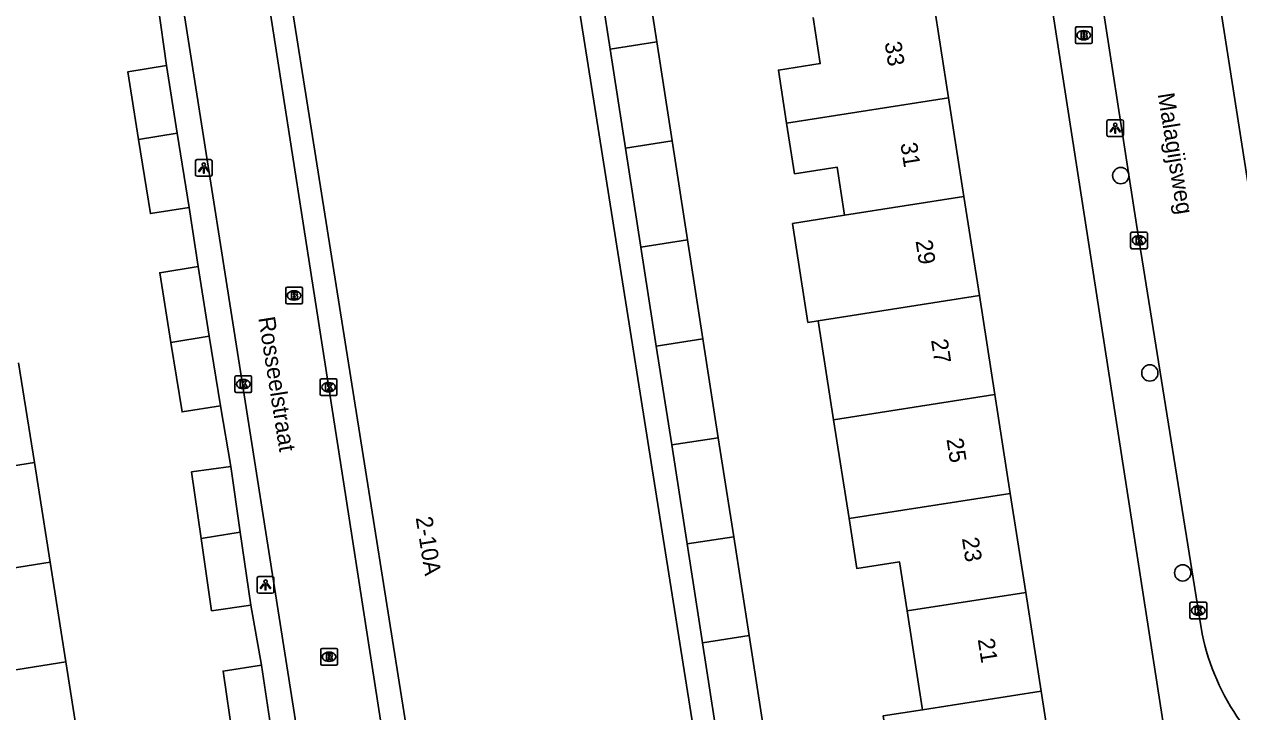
# Model space of a CAD drawing. Extents: x 160077 to 160945, y 386481 to 387498.
# Drawn here: x 160547.5 to 160620.3, y 387375.4 to 387416.6 of the extents above; entities that cross this region are included whole.
import ezdxf

# ---------------------------------------------------------------- set-up
doc = ezdxf.new("R2010")
doc.units = 0
for name, color, linetype in [('IMGEO_Boom', 7, 'Continuous'), ('IMGEO_Brandkraan', 7, 'Continuous'), ('IMGEO_Kolk', 7, 'Continuous'), ('IMGEO_Lichtpunt', 7, 'Continuous'), ('IMGEO_Openbare_ruimte_label', 7, 'Continuous'), ('IMGEO_Pand', 7, 'Continuous'), ('IMGEO_Pand_nummerreeks', 7, 'Continuous'), ('IMGEO_Rijbaan_lokaal_open', 7, 'Continuous'), ('IMGEO_Rioolput', 7, 'Continuous'), ('IMGEO_Voetpad_open', 7, 'Continuous')]:
    doc.layers.add(name, color=color, linetype=linetype)

msp = doc.modelspace()

# ---------------------------------------------------------------- linework, layer by layer
at = {"layer": 'IMGEO_Boom'}
for centre in [(160613.231, 387407.572), (160614.973, 387395.746), (160616.944, 387383.768)]:
    msp.add_circle(centre, 0.489, dxfattribs=at)
at = {"layer": 'IMGEO_Brandkraan'}
for p, q in [((160610.507, 387415.558), (160610.507, 387416.41)), ((160610.582, 387416.484), (160611.434, 387416.484)), ((160610.995, 387416.264), (160611.02, 387416.264)), ((160611.508, 387416.41), (160611.508, 387415.558)), ((160611.434, 387415.484), (160610.582, 387415.484)), ((160611.018, 387415.704), (160610.993, 387415.704)), ((160563.241, 387400.891), (160564.093, 387400.891)), ((160563.166, 387399.965), (160563.166, 387400.817)), ((160563.677, 387400.111), (160563.652, 387400.111)), ((160563.654, 387400.671), (160563.679, 387400.671)), ((160564.167, 387400.817), (160564.167, 387399.965)), ((160564.093, 387399.891), (160563.241, 387399.891))]:
    msp.add_line(p, q, dxfattribs=at)
for points in [[(160610.507, 387415.558), (160610.507, 387416.41)], [(160610.582, 387416.484), (160611.434, 387416.484)], [(160610.855, 387416.184), (160610.855, 387415.784), (160611.068, 387415.784)], [(160611.086, 387416.184), (160610.855, 387416.184)], [(160611.508, 387416.41), (160611.508, 387415.558)], [(160611.434, 387415.484), (160610.582, 387415.484)], [(160611.034, 387416.103), (160610.98, 387416.103), (160610.98, 387416.027)], [(160610.98, 387416.027), (160611.033, 387416.027)], [(160611.042, 387415.951), (160610.98, 387415.951), (160610.98, 387415.87)], [(160610.98, 387415.87), (160611.042, 387415.87)], [(160563.241, 387400.891), (160564.093, 387400.891)], [(160563.166, 387399.965), (160563.166, 387400.817)], [(160563.514, 387400.591), (160563.514, 387400.191), (160563.727, 387400.191)], [(160563.745, 387400.591), (160563.514, 387400.591)], [(160563.693, 387400.51), (160563.639, 387400.51), (160563.639, 387400.434)], [(160563.639, 387400.434), (160563.692, 387400.434)], [(160563.701, 387400.358), (160563.639, 387400.358), (160563.639, 387400.277)], [(160563.639, 387400.277), (160563.701, 387400.277)], [(160564.167, 387400.817), (160564.167, 387399.965)], [(160564.093, 387399.891), (160563.241, 387399.891)]]:
    msp.add_lwpolyline(points, dxfattribs=at)
for centre, radius, start, end in [((160610.584, 387416.408), 0.0765, 91.55205, 178.44795), ((160610.584, 387416.408), 0.0765, 91.55205, 178.44795), ((160611.09, 387416.039), 0.145, 59.4692, 91.53667), ((160611.115, 387416.086), 0.0922, 285.51372, 58.15012), ((160611.432, 387416.408), 0.0765, 1.55205, 88.44795), ((160611.432, 387416.408), 0.0765, 1.55205, 88.44795), ((160610.584, 387415.56), 0.0765, 181.55205, 268.44795), ((160610.584, 387415.56), 0.0765, 181.55205, 268.44795), ((160611.035, 387416.065), 0.0379, 267.82845, 90.93552), ((160611.043, 387415.91), 0.0404, 269.87594, 90.50774), ((160611.074, 387416.035), 0.251, 268.66757, 293.53466), ((160611.12, 387415.894), 0.105, 301.31148, 78.98903), ((160611.432, 387415.56), 0.0765, 271.55205, 358.44795), ((160611.432, 387415.56), 0.0765, 271.55205, 358.44795), ((160563.243, 387400.815), 0.0765, 91.55205, 178.44795), ((160563.243, 387400.815), 0.0765, 91.55205, 178.44795), ((160564.091, 387400.815), 0.0765, 1.55205, 88.44795), ((160564.091, 387400.815), 0.0765, 1.55205, 88.44795), ((160563.694, 387400.472), 0.0379, 267.82845, 90.93552), ((160563.702, 387400.317), 0.0404, 269.87594, 90.50774), ((160563.733, 387400.442), 0.251, 268.66757, 293.53466), ((160563.749, 387400.446), 0.145, 59.4692, 91.53667), ((160563.774, 387400.493), 0.0922, 285.51372, 58.15012), ((160563.779, 387400.301), 0.105, 301.31148, 78.98903), ((160563.243, 387399.967), 0.0765, 181.55205, 268.44795), ((160563.243, 387399.967), 0.0765, 181.55205, 268.44795), ((160564.091, 387399.967), 0.0765, 271.55205, 358.44795), ((160564.091, 387399.967), 0.0765, 271.55205, 358.44795)]:
    msp.add_arc(centre, radius, start, end, dxfattribs=at)
for centre, major_axis, ratio, start_param, end_param in [((160610.994, 387415.984), (-0.387, 0.002), 0.722429, 4.712389, 7.853982), ((160611.019, 387415.984), (-0.39, 0.002), 0.717154, 1.570796, 4.712389), ((160563.653, 387400.391), (-0.387, 0.002), 0.722429, 4.712389, 7.853982), ((160563.678, 387400.391), (-0.39, 0.002), 0.717154, 1.570796, 4.712389)]:
    msp.add_ellipse(centre, major_axis=major_axis, ratio=ratio, start_param=start_param, end_param=end_param, dxfattribs=at)
at = {"layer": 'IMGEO_Kolk'}
for p, q in [((160613.824, 387403.267), (160613.824, 387404.119)), ((160613.899, 387404.193), (160614.751, 387404.193)), ((160614.312, 387403.973), (160614.337, 387403.973)), ((160614.825, 387404.119), (160614.825, 387403.267)), ((160614.751, 387403.193), (160613.899, 387403.193)), ((160614.335, 387403.413), (160614.31, 387403.413)), ((160560.121, 387394.656), (160560.121, 387395.508)), ((160560.196, 387395.582), (160561.048, 387395.582)), ((160560.609, 387395.362), (160560.634, 387395.362)), ((160561.122, 387395.508), (160561.122, 387394.656)), ((160565.236, 387394.469), (160565.236, 387395.321)), ((160565.311, 387395.395), (160566.163, 387395.395)), ((160565.724, 387395.175), (160565.749, 387395.175)), ((160566.237, 387395.321), (160566.237, 387394.469)), ((160561.048, 387394.582), (160560.196, 387394.582)), ((160560.632, 387394.802), (160560.607, 387394.802)), ((160566.163, 387394.395), (160565.311, 387394.395)), ((160565.747, 387394.615), (160565.722, 387394.615)), ((160617.38, 387381.086), (160617.38, 387381.938)), ((160617.455, 387382.012), (160618.307, 387382.012)), ((160618.381, 387381.938), (160618.381, 387381.086)), ((160617.891, 387381.232), (160617.866, 387381.232)), ((160617.868, 387381.792), (160617.893, 387381.792)), ((160618.307, 387381.012), (160617.455, 387381.012))]:
    msp.add_line(p, q, dxfattribs=at)
for points in [[(160613.824, 387403.267), (160613.824, 387404.119)], [(160613.899, 387404.193), (160614.751, 387404.193)], [(160614.145, 387403.893), (160614.268, 387403.893), (160614.268, 387403.742), (160614.398, 387403.893), (160614.562, 387403.893), (160614.416, 387403.742), (160614.569, 387403.493), (160614.417, 387403.493), (160614.332, 387403.657), (160614.268, 387403.59), (160614.268, 387403.493), (160614.145, 387403.493), (160614.145, 387403.893)], [(160614.825, 387404.119), (160614.825, 387403.267)], [(160614.751, 387403.193), (160613.899, 387403.193)], [(160560.121, 387394.656), (160560.121, 387395.508)], [(160560.196, 387395.582), (160561.048, 387395.582)], [(160560.442, 387395.282), (160560.565, 387395.282), (160560.565, 387395.131), (160560.695, 387395.282), (160560.859, 387395.282), (160560.713, 387395.131), (160560.866, 387394.882), (160560.714, 387394.882), (160560.629, 387395.046), (160560.565, 387394.979), (160560.565, 387394.882), (160560.442, 387394.882), (160560.442, 387395.282)], [(160561.122, 387395.508), (160561.122, 387394.656)], [(160565.236, 387394.469), (160565.236, 387395.321)], [(160565.311, 387395.395), (160566.163, 387395.395)], [(160565.557, 387395.095), (160565.68, 387395.095), (160565.68, 387394.944), (160565.81, 387395.095), (160565.974, 387395.095), (160565.828, 387394.944), (160565.981, 387394.695), (160565.829, 387394.695), (160565.744, 387394.859), (160565.68, 387394.792), (160565.68, 387394.695), (160565.557, 387394.695), (160565.557, 387395.095)], [(160566.237, 387395.321), (160566.237, 387394.469)], [(160561.048, 387394.582), (160560.196, 387394.582)], [(160566.163, 387394.395), (160565.311, 387394.395)], [(160617.38, 387381.086), (160617.38, 387381.938)], [(160617.455, 387382.012), (160618.307, 387382.012)], [(160618.381, 387381.938), (160618.381, 387381.086)], [(160617.701, 387381.712), (160617.824, 387381.712), (160617.824, 387381.561), (160617.954, 387381.712), (160618.118, 387381.712), (160617.972, 387381.561), (160618.125, 387381.312), (160617.973, 387381.312), (160617.888, 387381.476), (160617.824, 387381.409), (160617.824, 387381.312), (160617.701, 387381.312), (160617.701, 387381.712)], [(160618.307, 387381.012), (160617.455, 387381.012)]]:
    msp.add_lwpolyline(points, dxfattribs=at)
for centre, start, end in [((160613.901, 387404.117), 91.55205, 178.44795), ((160613.901, 387404.117), 91.55205, 178.44795), ((160614.749, 387404.117), 1.55205, 88.44795), ((160614.749, 387404.117), 1.55205, 88.44795), ((160613.901, 387403.269), 181.55205, 268.44795), ((160613.901, 387403.269), 181.55205, 268.44795), ((160614.749, 387403.269), 271.55205, 358.44795), ((160614.749, 387403.269), 271.55205, 358.44795), ((160560.198, 387395.506), 91.55205, 178.44795), ((160560.198, 387395.506), 91.55205, 178.44795), ((160561.046, 387395.506), 1.55205, 88.44795), ((160561.046, 387395.506), 1.55205, 88.44795), ((160565.313, 387395.319), 91.55205, 178.44795), ((160565.313, 387395.319), 91.55205, 178.44795), ((160566.161, 387395.319), 1.55205, 88.44795), ((160566.161, 387395.319), 1.55205, 88.44795), ((160560.198, 387394.658), 181.55205, 268.44795), ((160560.198, 387394.658), 181.55205, 268.44795), ((160561.046, 387394.658), 271.55205, 358.44795), ((160561.046, 387394.658), 271.55205, 358.44795), ((160565.313, 387394.471), 181.55205, 268.44795), ((160565.313, 387394.471), 181.55205, 268.44795), ((160566.161, 387394.471), 271.55205, 358.44795), ((160566.161, 387394.471), 271.55205, 358.44795), ((160617.457, 387381.936), 91.55205, 178.44795), ((160617.457, 387381.936), 91.55205, 178.44795), ((160618.305, 387381.936), 1.55205, 88.44795), ((160618.305, 387381.936), 1.55205, 88.44795), ((160617.457, 387381.088), 181.55205, 268.44795), ((160617.457, 387381.088), 181.55205, 268.44795), ((160618.305, 387381.088), 271.55205, 358.44795), ((160618.305, 387381.088), 271.55205, 358.44795)]:
    msp.add_arc(centre, 0.0765, start, end, dxfattribs=at)
for centre, major_axis, ratio, start_param, end_param in [((160614.311, 387403.693), (-0.387, 0.002), 0.722429, 4.712389, 7.853982), ((160614.336, 387403.693), (-0.39, 0.002), 0.717154, 1.570796, 4.712389), ((160560.608, 387395.082), (-0.387, 0.002), 0.722429, 4.712389, 7.853982), ((160560.633, 387395.082), (-0.39, 0.002), 0.717154, 1.570796, 4.712389), ((160565.723, 387394.895), (-0.387, 0.002), 0.722429, 4.712389, 7.853982), ((160565.748, 387394.895), (-0.39, 0.002), 0.717154, 1.570796, 4.712389), ((160617.867, 387381.512), (-0.387, 0.002), 0.722429, 4.712389, 7.853982), ((160617.892, 387381.512), (-0.39, 0.002), 0.717154, 1.570796, 4.712389)]:
    msp.add_ellipse(centre, major_axis=major_axis, ratio=ratio, start_param=start_param, end_param=end_param, dxfattribs=at)
at = {"layer": 'IMGEO_Lichtpunt'}
for p, q in [((160612.401, 387410.82), (160612.401, 387410.013)), ((160612.401, 387410.82), (160612.401, 387410.013)), ((160613.303, 387410.915), (160612.495, 387410.915)), ((160613.303, 387410.915), (160612.495, 387410.915)), ((160613.397, 387410.013), (160613.397, 387410.82)), ((160613.397, 387410.013), (160613.397, 387410.82)), ((160612.495, 387409.919), (160613.303, 387409.919)), ((160612.495, 387409.919), (160613.303, 387409.919)), ((160557.753, 387408.435), (160557.753, 387407.628)), ((160557.753, 387408.435), (160557.753, 387407.628)), ((160558.655, 387408.53), (160557.847, 387408.53)), ((160558.655, 387408.53), (160557.847, 387408.53)), ((160558.749, 387407.628), (160558.749, 387408.435)), ((160558.749, 387407.628), (160558.749, 387408.435)), ((160557.847, 387407.534), (160558.655, 387407.534)), ((160557.847, 387407.534), (160558.655, 387407.534)), ((160561.455, 387383.45), (160561.455, 387382.643)), ((160561.455, 387383.45), (160561.455, 387382.643)), ((160562.357, 387383.545), (160561.549, 387383.545)), ((160562.357, 387383.545), (160561.549, 387383.545)), ((160562.451, 387382.643), (160562.451, 387383.45)), ((160562.451, 387382.643), (160562.451, 387383.45)), ((160561.549, 387382.549), (160562.357, 387382.549)), ((160561.549, 387382.549), (160562.357, 387382.549))]:
    msp.add_line(p, q, dxfattribs=at)
for points in [[(160612.775, 387410.484), (160612.814, 387410.456), (160612.626, 387410.194), (160612.588, 387410.221), (160612.775, 387410.484)], [(160612.877, 387410.436), (160612.924, 387410.436), (160612.924, 387410.114), (160612.877, 387410.114), (160612.877, 387410.436)], [(160612.987, 387410.456), (160613.025, 387410.483), (160613.212, 387410.221), (160613.173, 387410.193), (160612.987, 387410.456)], [(160558.127, 387408.099), (160558.166, 387408.071), (160557.978, 387407.809), (160557.94, 387407.836), (160558.127, 387408.099)], [(160558.229, 387408.051), (160558.276, 387408.051), (160558.276, 387407.729), (160558.229, 387407.729), (160558.229, 387408.051)], [(160558.339, 387408.071), (160558.377, 387408.098), (160558.564, 387407.836), (160558.525, 387407.808), (160558.339, 387408.071)], [(160561.829, 387383.114), (160561.868, 387383.086), (160561.68, 387382.824), (160561.642, 387382.851), (160561.829, 387383.114)], [(160561.931, 387383.066), (160561.978, 387383.066), (160561.978, 387382.744), (160561.931, 387382.744), (160561.931, 387383.066)], [(160562.041, 387383.086), (160562.079, 387383.113), (160562.266, 387382.851), (160562.227, 387382.823), (160562.041, 387383.086)]]:
    msp.add_lwpolyline(points, dxfattribs=at)
for centre in [(160612.9, 387410.618), (160558.252, 387408.233), (160561.954, 387383.248)]:
    msp.add_circle(centre, 0.0994, dxfattribs=at)
for centre, start, end in [((160612.495, 387410.82), 90, 180), ((160612.495, 387410.82), 90, 180), ((160613.303, 387410.82), 0, 90), ((160613.303, 387410.82), 0, 90), ((160612.495, 387410.013), 180, 270), ((160612.495, 387410.013), 180, 270), ((160613.303, 387410.013), 270, 0), ((160613.303, 387410.013), 270, 360), ((160557.847, 387408.435), 90, 180), ((160557.847, 387408.435), 90, 180), ((160558.655, 387408.435), 0, 90), ((160558.655, 387408.435), 0, 90), ((160557.847, 387407.628), 180, 270), ((160557.847, 387407.628), 180, 270), ((160558.655, 387407.628), 270, 0), ((160558.655, 387407.628), 270, 360), ((160561.549, 387383.45), 90, 180), ((160561.549, 387383.45), 90, 180), ((160562.357, 387383.45), 0, 90), ((160562.357, 387383.45), 0, 90), ((160561.549, 387382.643), 180, 270), ((160561.549, 387382.643), 180, 270), ((160562.357, 387382.643), 270, 0), ((160562.357, 387382.643), 270, 360)]:
    msp.add_arc(centre, 0.0946, start, end, dxfattribs=at)
at = {"layer": 'IMGEO_Pand'}
for points in [[(160575.523, 387450.574), (160576.464, 387444.648), (160591.839, 387347.839)], [(160577.677, 387328.687), (160559.841, 387440.996)], [(160584.498, 387421.512), (160585.419, 387415.584)], [(160582.621, 387415.147), (160581.701, 387421.075)], [(160601.98, 387418.168), (160602.905, 387412.24)], [(160593.199, 387410.725), (160592.704, 387413.897), (160595.213, 387414.289), (160594.783, 387417.045)], [(160585.419, 387415.584), (160582.621, 387415.147)], [(160585.419, 387415.584), (160586.34, 387409.654)], [(160583.542, 387409.218), (160582.621, 387415.147)], [(160554.347, 387409.743), (160553.702, 387413.798), (160556.017, 387414.166)], [(160556.017, 387414.166), (160556.663, 387410.108)], [(160602.905, 387412.24), (160593.199, 387410.725)], [(160602.905, 387412.24), (160603.83, 387406.312)], [(160596.669, 387405.194), (160596.218, 387408.086), (160593.673, 387407.689), (160593.199, 387410.725)], [(160554.347, 387409.743), (160556.663, 387410.108)], [(160557.37, 387405.661), (160555.055, 387405.293), (160554.347, 387409.743)], [(160556.663, 387410.108), (160557.37, 387405.661)], [(160583.542, 387409.218), (160586.34, 387409.654)], [(160586.34, 387409.654), (160587.261, 387403.725)], [(160584.463, 387403.288), (160583.542, 387409.218)], [(160603.83, 387406.312), (160596.669, 387405.194)], [(160603.83, 387406.312), (160604.756, 387400.383)], [(160595.09, 387398.874), (160594.475, 387398.778), (160593.551, 387404.694), (160596.669, 387405.194)], [(160587.261, 387403.725), (160584.463, 387403.288)], [(160585.384, 387397.359), (160584.463, 387403.288)], [(160587.261, 387403.725), (160588.182, 387397.796)], [(160556.284, 387397.581), (160555.616, 387401.749), (160557.907, 387402.117)], [(160557.907, 387402.117), (160558.576, 387397.949)], [(160604.756, 387400.383), (160595.09, 387398.874)], [(160605.681, 387394.455), (160604.756, 387400.383)], [(160595.09, 387398.874), (160596.015, 387392.946)], [(160558.576, 387397.949), (160556.284, 387397.581)], [(160558.576, 387397.949), (160559.244, 387393.781)], [(160559.244, 387393.781), (160556.953, 387393.413), (160556.284, 387397.581)], [(160585.384, 387397.359), (160588.182, 387397.796)], [(160586.305, 387391.43), (160585.384, 387397.359)], [(160588.182, 387397.796), (160589.102, 387391.867)], [(160547.152, 387396.351), (160548.094, 387390.376)], [(160596.015, 387392.946), (160605.681, 387394.455)], [(160605.681, 387394.455), (160606.607, 387388.527)], [(160596.941, 387387.017), (160596.015, 387392.946)], [(160589.102, 387391.867), (160586.305, 387391.43)], [(160587.226, 387385.499), (160586.305, 387391.43)], [(160589.102, 387391.867), (160590.023, 387385.936)], [(160548.094, 387390.376), (160540.71, 387389.212)], [(160548.094, 387390.376), (160549.037, 387384.402)], [(160558.094, 387385.831), (160557.521, 387389.812), (160559.872, 387390.151)], [(160559.872, 387390.151), (160560.44, 387386.201)], [(160606.607, 387388.527), (160596.941, 387387.017)], [(160606.607, 387388.527), (160607.532, 387382.599)], [(160600.425, 387381.49), (160599.968, 387384.419), (160597.409, 387384.02), (160596.941, 387387.017)], [(160558.094, 387385.831), (160560.44, 387386.201)], [(160561.067, 387381.838), (160558.717, 387381.499), (160558.094, 387385.831)], [(160560.44, 387386.201), (160561.067, 387381.838)], [(160590.023, 387385.936), (160587.226, 387385.499)], [(160590.023, 387385.936), (160590.944, 387380.011)], [(160588.146, 387379.574), (160587.226, 387385.499)], [(160549.037, 387384.402), (160541.652, 387383.238)], [(160549.037, 387384.402), (160549.979, 387378.429)], [(160607.532, 387382.599), (160600.425, 387381.49)], [(160607.532, 387382.599), (160608.457, 387376.671)], [(160601.351, 387375.561), (160601.332, 387375.681), (160600.425, 387381.49)], [(160588.146, 387379.574), (160590.944, 387380.011)], [(160590.944, 387380.011), (160591.865, 387374.08)], [(160589.067, 387373.643), (160588.146, 387379.574)], [(160542.594, 387377.265), (160549.979, 387378.429)], [(160549.979, 387378.429), (160550.921, 387372.455)], [(160559.999, 387373.881), (160559.404, 387377.885), (160561.717, 387378.228)], [(160561.717, 387378.228), (160562.309, 387374.245)], [(160601.351, 387375.561), (160608.457, 387376.671)], [(160608.457, 387376.671), (160609.383, 387370.743)], [(160602.187, 387369.629), (160599.904, 387369.273), (160598.98, 387375.191), (160601.351, 387375.561)]]:
    msp.add_lwpolyline(points, dxfattribs=at)
at = {"layer": 'IMGEO_Rijbaan_lokaal_open'}
for points in [[(160571.264, 387326.474), (160566.063, 387360.17), (160551.976, 387449.649)], [(160558.566, 387440.793), (160560.933, 387425.732), (160566.779, 387388.194), (160571.754, 387356.264), (160576.092, 387327.919)], [(160618.318, 387423.36), (160618.371, 387422.985), (160624.877, 387381.437)], [(160618.109, 387380.11), (160617.91, 387381.338), (160614.175, 387404.637), (160611.642, 387421.037)]]:
    msp.add_lwpolyline(points, dxfattribs=at)
msp.add_arc((160632.079, 387383.09), 14.285, 192.04291, 215.18149, dxfattribs=at)
at = {"layer": 'IMGEO_Rioolput'}
for p, q in [((160565.265, 387378.314), (160565.265, 387379.166)), ((160565.34, 387379.24), (160566.192, 387379.24)), ((160565.753, 387379.02), (160565.778, 387379.02)), ((160566.266, 387379.166), (160566.266, 387378.314)), ((160565.776, 387378.46), (160565.751, 387378.46)), ((160566.192, 387378.24), (160565.34, 387378.24))]:
    msp.add_line(p, q, dxfattribs=at)
for points in [[(160565.265, 387378.314), (160565.265, 387379.166)], [(160565.34, 387379.24), (160566.192, 387379.24)], [(160566.266, 387379.166), (160566.266, 387378.314)], [(160565.854, 387378.938), (160565.602, 387378.94), (160565.602, 387378.54)], [(160565.602, 387378.54), (160565.726, 387378.54), (160565.726, 387378.702), (160565.737, 387378.702)], [(160565.78, 387378.859), (160565.726, 387378.859), (160565.726, 387378.778)], [(160565.726, 387378.778), (160565.778, 387378.778)], [(160565.784, 387378.673), (160565.855, 387378.54), (160565.995, 387378.54), (160565.93, 387378.666)], [(160566.192, 387378.24), (160565.34, 387378.24)]]:
    msp.add_lwpolyline(points, dxfattribs=at)
for centre, radius, start, end in [((160565.342, 387379.164), 0.0765, 91.55205, 178.44795), ((160565.342, 387379.164), 0.0765, 91.55205, 178.44795), ((160566.19, 387379.164), 0.0765, 1.55205, 88.44795), ((160566.19, 387379.164), 0.0765, 1.55205, 88.44795), ((160565.342, 387378.316), 0.0765, 181.55205, 268.44795), ((160565.342, 387378.316), 0.0765, 181.55205, 268.44795), ((160565.736, 387378.649), 0.0533, 26.02933, 88.69889), ((160565.762, 387378.967), 0.19, 274.7715, 282.96867), ((160565.786, 387378.763), 0.0964, 77.00612, 93.18647), ((160565.8, 387378.82), 0.0378, 276.66336, 79.67722), ((160565.853, 387378.828), 0.109, 350.36119, 89.41601), ((160565.851, 387378.828), 0.112, 277.58423, 350.98172), ((160565.835, 387378.613), 0.108, 29.51342, 73.79051), ((160566.19, 387378.316), 0.0765, 271.55205, 358.44795), ((160566.19, 387378.316), 0.0765, 271.55205, 358.44795)]:
    msp.add_arc(centre, radius, start, end, dxfattribs=at)
for centre, major_axis, ratio, start_param, end_param in [((160565.752, 387378.74), (-0.387, 0.002), 0.722429, 4.712389, 7.853982), ((160565.777, 387378.74), (-0.39, 0.002), 0.717154, 1.570796, 4.712389)]:
    msp.add_ellipse(centre, major_axis=major_axis, ratio=ratio, start_param=start_param, end_param=end_param, dxfattribs=at)
at = {"layer": 'IMGEO_Voetpad_open'}
for points in [[(160617.393, 387364.36), (160606.344, 387435.512)], [(160555.516, 387417.73), (160556.017, 387414.166)], [(160557.37, 387405.661), (160557.907, 387402.117)], [(160559.244, 387393.781), (160559.872, 387390.151)], [(160561.067, 387381.838), (160561.717, 387378.228)]]:
    msp.add_lwpolyline(points, dxfattribs=at)

# ---------------------------------------------------------------- texts
at = {"layer": 'IMGEO_Openbare_ruimte_label'}
for s, rotation, p in [('Malagijsweg', 279.0948, (160615.442, 387412.459)), ('Rosseelstraat', 278.97263, (160561.519, 387399.048))]:
    msp.add_text(s, height=1, rotation=rotation, dxfattribs=at).set_placement(p)
at = {"layer": 'IMGEO_Pand_nummerreeks'}
for s, rotation, p in [('33', 278.87211, (160599.07, 387415.542)), ('31', 278.87211, (160600.014, 387409.489)), ('29', 278.87491, (160600.925, 387403.658)), ('27', 278.87491, (160601.852, 387397.716)), ('25', 278.87211, (160602.78, 387391.776)), ('2-10A', 279.024, (160570.956, 387387.073)), ('23', 278.87211, (160603.707, 387385.834)), ('21', 278.87491, (160604.652, 387379.78))]:
    msp.add_text(s, height=1, rotation=rotation, dxfattribs=at).set_placement(p)

doc.saveas('drawing.dxf')
